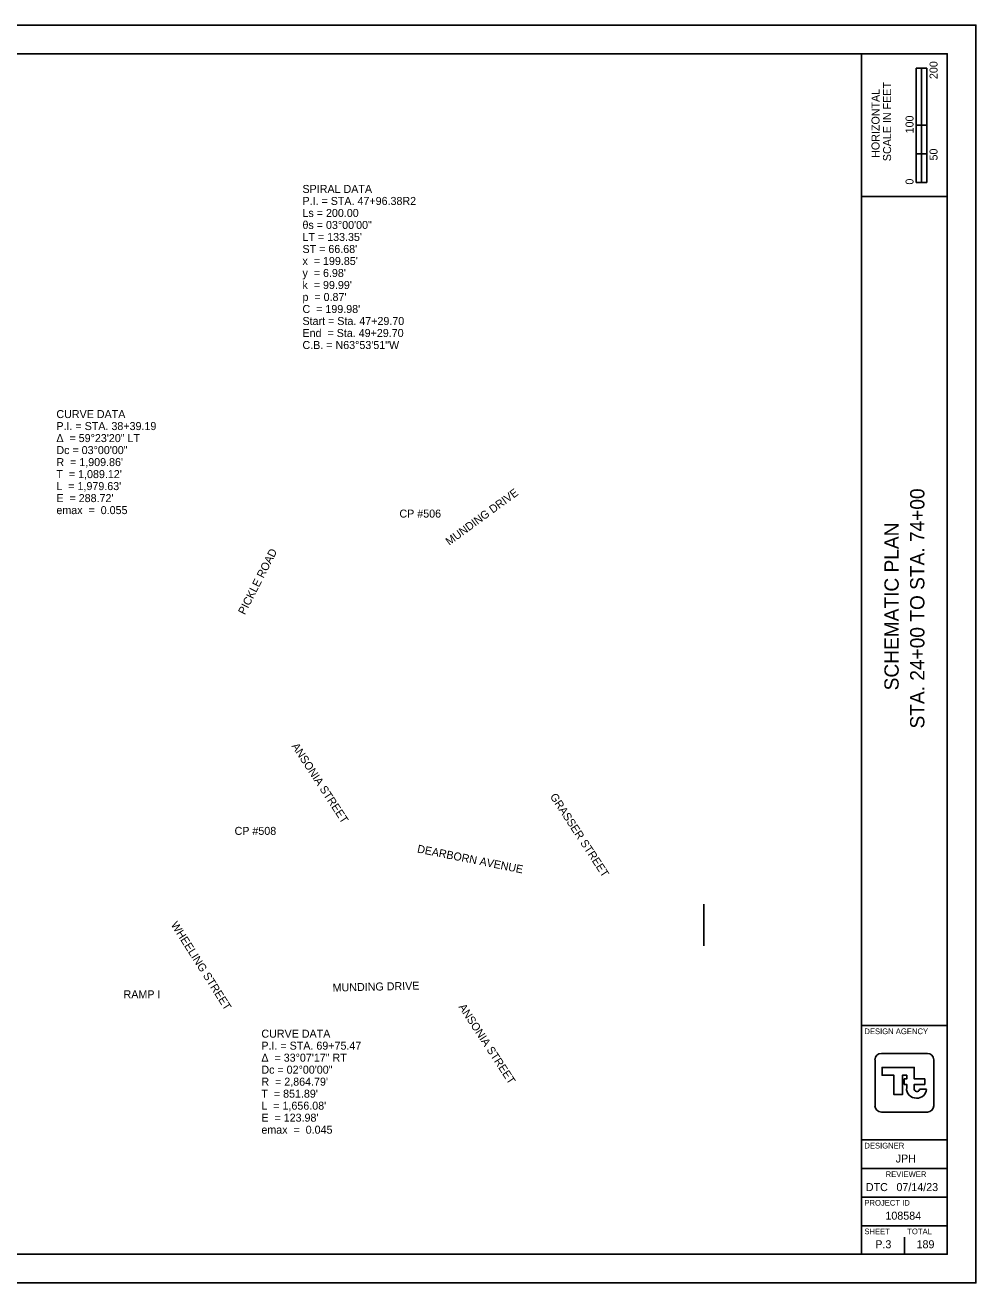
# Model space of a CAD drawing. Extents: x -1.8 to 34, y 0 to 22.
# Drawn here: x 17.37 to 34, y 0 to 22 of the extents above; entities that cross this region are included whole.
import ezdxf

# ---------------------------------------------------------------- set-up
doc = ezdxf.new("R2010")
doc.units = 0
for name, color, linetype in [('Default', 7, 'Continuous'), ('RW_X_CL_100_Curve_Data', 7, 'Continuous'), ('SH_Border', 7, 'Continuous'), ('SH_Cut_Line', 7, 'Continuous'), ('SH_Data', 7, 'Continuous'), ('SH_Text', 7, 'Continuous')]:
    doc.layers.add(name, color=color, linetype=linetype)

msp = doc.modelspace()

# ---------------------------------------------------------------- linework, layer by layer
at = {"layer": 'RW_X_CL_100_Curve_Data'}
msp.add_line((29.244, 6.624), (29.244, 5.898), dxfattribs=at)
at = {"layer": 'SH_Border'}
for p, q in [((32, 0.5), (32, 21.5)), ((32, 19), (33.5, 19)), ((32, 4.5), (33.5, 4.5)), ((32, 2.5), (33.5, 2.5)), ((32, 2), (33.5, 2)), ((32, 1.5), (33.5, 1.5)), ((32, 1), (33.5, 1))]:
    msp.add_line(p, q, dxfattribs=at)
msp.add_lwpolyline([(1.5, 21.5), (33.5, 21.5), (33.5, 0.5), (1.5, 0.5)], close=True, dxfattribs=at)
at = {"layer": 'SH_Cut_Line'}
msp.add_lwpolyline([(0, 0), (34, 0), (34, 22), (0, 22)], close=True, dxfattribs=at)
at = {"layer": 'SH_Data'}
for p, q in [((32.957, 19.25), (32.957, 21.25)), ((33.144, 21.25), (32.957, 21.25)), ((32.957, 20.25), (32.957, 21.25)), ((32.957, 21.25), (33.05, 21.25)), ((33.05, 21.25), (33.051, 21.25)), ((33.051, 21.25), (33.051, 20.25)), ((33.144, 21.25), (33.144, 19.25)), ((33.051, 20.25), (32.957, 20.25)), ((33.143, 20.25), (33.05, 20.25)), ((33.05, 20.25), (33.05, 19.75)), ((33.143, 19.75), (33.143, 20.25)), ((33.05, 19.75), (32.957, 19.75)), ((32.957, 19.75), (32.957, 19.25)), ((33.05, 19.25), (33.05, 19.75)), ((33.05, 19.75), (33.143, 19.75)), ((33.144, 19.25), (32.957, 19.25)), ((32.957, 19.25), (33.05, 19.25)), ((32.75, 3.5), (32.75, 3.5)), ((32.791, 3.415), (32.791, 3.415)), ((33.136, 3.385), (33.015, 3.385)), ((32.375, 0.675), (32.375, 0.675)), ((32.75, 0.5), (32.75, 0.8))]:
    msp.add_line(p, q, dxfattribs=at)
for points in [[(32.348, 4.014), (33.152, 4.014)], [(32.236, 3.099), (32.236, 3.901)], [(32.922, 3.399), (32.922, 3.47), (33.107, 3.47), (33.107, 3.568), (32.922, 3.568), (32.922, 3.768), (32.361, 3.768), (32.361, 3.632), (32.566, 3.632), (32.566, 3.294), (32.715, 3.294), (32.715, 3.63), (32.79, 3.63), (32.79, 3.568), (32.748, 3.568), (32.748, 3.47), (32.79, 3.47), (32.79, 3.415), (32.791, 3.415)], [(33.264, 3.901), (33.264, 3.099)], [(33.152, 2.986), (32.348, 2.986)]]:
    msp.add_lwpolyline(points, dxfattribs=at)
for centre, radius, start, end in [((32.348, 3.901), 0.113, 90, 180), ((33.152, 3.901), 0.113, 360, 90), ((32.949, 3.392), 0.16, 171.8856, 274.8323), ((32.968, 3.392), 0.0473, 171.8856, 350.9243), ((32.976, 3.392), 0.16, 265.1677, 357.3201), ((32.348, 3.099), 0.113, 180, 270), ((33.152, 3.099), 0.113, 270, 360)]:
    msp.add_arc(centre, radius, start, end, dxfattribs=at)

# ---------------------------------------------------------------- texts
at = {"layer": 'Default'}
msp.add_text('ANSONIA STREET', height=0.14, rotation=303.1358, dxfattribs=at).set_placement((24.945, 4.827))
at = {"layer": 'RW_X_CL_100_Curve_Data'}
for s, p in [('SPIRAL DATA', (22.22, 19.065)), ('P.I. = STA. 47+96.38R2', (22.22, 18.855)), ('Ls = 200.00', (22.22, 18.645)), ('θs = 03°00\'00"', (22.22, 18.435)), ("LT = 133.35'", (22.22, 18.225)), ("ST = 66.68'", (22.22, 18.015)), ("x  = 199.85'", (22.22, 17.805)), ("y  = 6.98'", (22.22, 17.595)), ("k  = 99.99'", (22.22, 17.385)), ("p  = 0.87'", (22.22, 17.175)), ("C  = 199.98'", (22.22, 16.965)), ('Start = Sta. 47+29.70', (22.22, 16.755)), ('End  = Sta. 49+29.70', (22.22, 16.545)), ('C.B. = N63°53\'51"W', (22.22, 16.335)), ('CURVE DATA', (17.915, 15.127)), ('P.I. = STA. 38+39.19', (17.915, 14.917)), ('Δ  = 59°23\'20" LT', (17.915, 14.707)), ('Dc = 03°00\'00"', (17.915, 14.497)), ("R  = 1,909.86'", (17.915, 14.287)), ("T  = 1,089.12'", (17.915, 14.077)), ("L  = 1,979.63'", (17.915, 13.867)), ("E  = 288.72'", (17.915, 13.657)), ('emax  =  0.055', (17.915, 13.447)), ('CURVE DATA', (21.501, 4.289)), ('P.I. = STA. 69+75.47', (21.501, 4.079)), ('Δ  = 33°07\'17" RT', (21.501, 3.869)), ('Dc = 02°00\'00"', (21.501, 3.659)), ("R  = 2,864.79'", (21.501, 3.449)), ("T  = 851.89'", (21.501, 3.239)), ("L  = 1,656.08'", (21.501, 3.029)), ("E  = 123.98'", (21.501, 2.819)), ('emax  =  0.045', (21.501, 2.609))]:
    msp.add_text(s, height=0.14, dxfattribs=at).set_placement(p)
at = {"layer": 'SH_Data'}
for s, height, p in [('200', 0.14, (33.33, 21.057)), ('SCALE IN FEET', 0.14, (32.517, 19.621)), ('HORIZONTAL', 0.14, (32.315, 19.679)), ('100', 0.14, (32.91, 20.107)), ('50', 0.14, (33.33, 19.633)), ('0', 0.14, (32.91, 19.211)), ('STA. 24+00 TO STA. 74+00', 0.25, (33.1, 9.697)), ('SCHEMATIC PLAN', 0.25, (32.65, 10.364))]:
    msp.add_text(s, height=height, rotation=90, dxfattribs=at).set_placement(p)
for s, height, p in [('DESIGN AGENCY', 0.1, (32.05, 4.35)), ('DESIGNER', 0.1, (32.05, 2.35)), ('JPH', 0.14, (32.598, 2.105)), ('REVIEWER', 0.1, (32.422, 1.85)), ('DTC', 0.14, (32.076, 1.605)), ('07/14/23', 0.14, (32.611, 1.605)), ('PROJECT ID', 0.1, (32.05, 1.35)), ('108584', 0.14, (32.418, 1.105)), ('SHEET', 0.1, (32.05, 0.85)), ('TOTAL', 0.1, (32.8, 0.85)), ('P.3', 0.14, (32.241, 0.605)), ('189', 0.14, (32.963, 0.605))]:
    msp.add_text(s, height=height, dxfattribs=at).set_placement(p)
at = {"layer": 'SH_Text'}
for s, rotation, p in [('MUNDING DRIVE', 36.3646, (24.788, 12.893)), ('PICKLE ROAD', 63.0233, (21.211, 11.676)), ('ANSONIA STREET', 303.1358, (22.024, 9.389)), ('GRASSER STREET', 303.1407, (26.543, 8.508)), ('DEARBORN AVENUE', 348.7264, (24.218, 7.529)), ('WHEELING STREET', 302.2713, (19.911, 6.265)), ('MUNDING DRIVE', 1.3324, (22.749, 5.094))]:
    msp.add_text(s, height=0.14, rotation=rotation, dxfattribs=at).set_placement(p)
for s, p in [('CP #506', (23.916, 13.386)), ('CP #508', (21.032, 7.836)), ('RAMP I', (19.09, 4.977))]:
    msp.add_text(s, height=0.14, dxfattribs=at).set_placement(p)

doc.saveas('drawing.dxf')
